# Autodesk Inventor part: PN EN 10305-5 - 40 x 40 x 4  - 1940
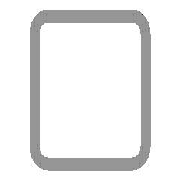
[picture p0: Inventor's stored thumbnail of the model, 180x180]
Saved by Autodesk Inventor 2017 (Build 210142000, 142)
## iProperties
_CCFamilyMember: 29
_CCFamilyDisplayName: PN EN 10305-5 (Rury kwadratowe, spawane, wymiarowane na zimno) - Rury stalowe do zastosowań precyzyjnych -  (Część 5: Rury kwadratowe, spawane, wymiarowane na z
_FrameMemberDoc: Frame Member File
_Version: 15.0.0
_GetPNFromCC: 1
Created: 2016-02
Part Number: PN EN 10305-5 - 40 x 40 x 4  - 1940
Material: Stal, miękka
Description: Rury stalowe do zastosowań precyzyjnych -  (Część 5: Rury kwadratowe, spawane, wymiarowane na zimno)
Document SubType Name: Modeling
Standard: PN
Designer: WindowsX
Standards Organization: PN
Language: pl-PL
Size Designation: 40 x 40 x 4
Categories: <MemberInstance><Categories><Category DisplayName="Kształtowniki konstrukcyjne" InternalName="089c4875-fa83-4c05-b084-43b9cc11f5ed" Mnemonic="GRDR"><CategoryPar
Stock Number: 40 x 40 x 4
Density: 7.85 g/cm^3
Appearance: Częściowo polerowana
Mass: 8060.75 g
Surface Area: 5144.82 cm^2
Volume: 1026.85 cm^3
IsCustomPart: 1
G_W: 40,000 mm
G_H: 40,000 mm
G_L: 1940,000 mm
Author: WindowsX
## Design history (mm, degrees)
node "Płaszczyzna początkowa"
node "Płaszczyzna końcowa"
sketch "Szkic"
  geometry: L1 (-20, -11.2)-(-20, 11.2); L2 (-11.2, 20)-(11.2, 20); L3 (20, 11.2)-(20, -11.2); L4 (11.2, -20)-(-11.2, -20); L5 (-11.2, 16)-(11.2, 16); L6 (16, 11.2)-(16, -11.2); L7 (11.2, -16)-(-11.2, -16); L8 (-16, -11.2)-(-16, 11.2); L9 (0, 30.552)-(0, -30.552) reference; L10 (-30.552, 0)-(30.552, 0) reference; A1 r 8.8 centre (-11.2, -11.2) between (-20, -11.2) and (-11.2, -20); A2 r 8.8 centre (-11.2, 11.2) between (-11.2, 20) and (-20, 11.2); A3 r 8.8 centre (11.2, 11.2) between (20, 11.2) and (11.2, 20); A4 r 8.8 centre (11.2, -11.2) between (11.2, -20) and (20, -11.2); A5 r 4.8 centre (-11.2, 11.2) between (-11.2, 16) and (-16, 11.2); A6 r 4.8 centre (11.2, 11.2) between (16, 11.2) and (11.2, 16); A7 r 4.8 centre (11.2, -11.2) between (11.2, -16) and (16, -11.2); A8 r 4.8 centre (-11.2, -11.2) between (-16, -11.2) and (-11.2, -16)
  constraints: 16 end point, 16 point on circle, 8 centre point, 8 tangent, 4 parallel, 3 equal radius, 2 perpendicular, 7 other
  dimensions: "d7" = 8.8 radius of A1 (= G_IR); "d10" = 40 distance between parallel lines of L2 L4 (= G_H); "d11" = 40 distance between parallel lines of L1 L3 (= G_W); "d12" = 4 distance between parallel lines of L3 L6 (= G_T); "d15" = 20 distance between parallel lines of L2 L10 (= 0.5 x d10); "d16" = 20 distance between parallel lines of L9 L3 (= 0.5 x d11)
extrude "Bryła" new body sketch "Szkic" stored distance "d3" = 1940 (= G_L); taper "d4" = 0 deg
node "Driven Length"
  sketch "Sketch3"
    geometry: L1 (0, 0)-(10, 0) reference
    constraints: 2 end point, 1 horizontal
  workplane "Work Plane3"
  sketch "Sketch4"
    geometry: L1 (-2, 0)-(12, 0) reference; L2 (-2, 1940)-(12, 1940) reference
    dimensions: "d18" = 1940 distance between parallel lines of L1 L2 (derived)
body "Solid1"
other parameters: "G_W" = 40 [user parameter; used in 1 equation term], "G_H" = 40 [user parameter; used in 1 equation term], "G_T" = 4 [user parameter; used in 1 equation term], "G_IR" = 8.8 [user parameter; used in 1 equation term], "G_L" = 1940 (= d18) [user parameter; used in 1 equation term], "G_OFFSET_START" = 0 [user parameter; used in 1 equation term], "G_OFFSET_END" = 0 [user parameter; used in 1 equation term], "d13" = 0 (computed from G_OFFSET_START), "d17" = 90 deg
